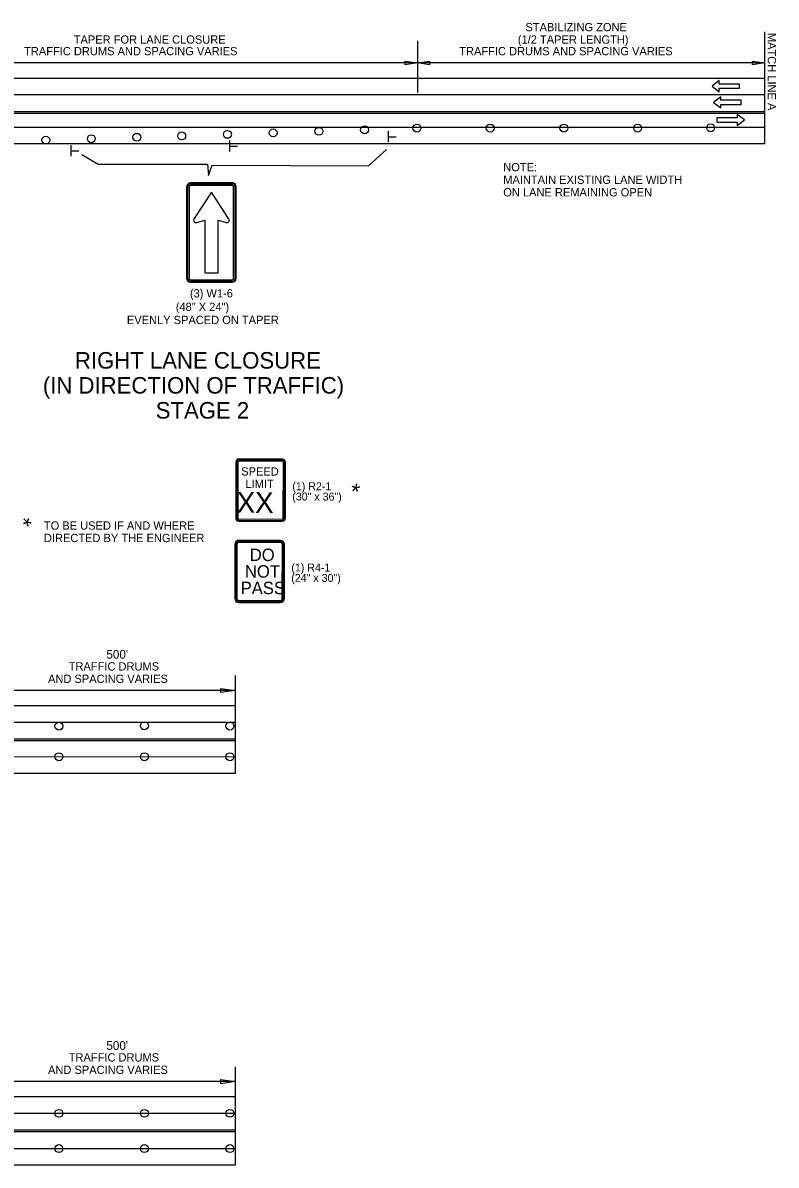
# Model space of a CAD drawing. Extents: x 1930579 to 1938013, y 596452 to 597673.
# Drawn here: x 1934532 to 1935078, y 596702 to 597530 of the extents above; entities that cross this region are included whole.
import ezdxf

# ---------------------------------------------------------------- set-up
doc = ezdxf.new("R2010")
doc.units = 0
for name, color, linetype in [('Default', 7, 'Continuous'), ('P_TC_Signs_Permanent', 7, 'Continuous'), ('R_Border', 7, 'Continuous'), ('R_Striping', 7, 'Continuous')]:
    doc.layers.add(name, color=color, linetype=linetype)

msp = doc.modelspace()

# ---------------------------------------------------------------- linework, layer by layer
at = {"layer": 'Default'}
for p, q in [((1935069.92, 597523.93), (1935069.92, 597466.19)), ((1934818.18, 597517.31), (1934818.18, 597480.01)), ((1934818.18, 597501.43), (1934450.97, 597501.43)), ((1934809.32, 597500.1), (1934809.32, 597502.76)), ((1934809.32, 597502.76), (1934818.18, 597501.43)), ((1934818.18, 597501.43), (1934809.32, 597500.1)), ((1934818.18, 597501.43), (1934827.05, 597502.76)), ((1935069.92, 597501.43), (1934818.18, 597501.43)), ((1934827.05, 597500.1), (1934818.18, 597501.43)), ((1934827.05, 597502.76), (1934827.05, 597500.1)), ((1935061.06, 597500.1), (1935061.06, 597502.76)), ((1935061.06, 597502.76), (1935069.92, 597501.43)), ((1935069.92, 597501.43), (1935061.06, 597500.1)), ((1935069.92, 597490.19), (1933755.41, 597490.19)), ((1935069.92, 597478.19), (1933755.41, 597478.19)), ((1935069.92, 597465.96), (1933755.41, 597465.96)), ((1935069.92, 597464.81), (1933755.41, 597464.81)), ((1935069.92, 597466.19), (1935069.92, 597442.63)), ((1935069.92, 597454.63), (1933755.41, 597454.63)), ((1934797.19, 597443.96), (1934797.19, 597451.94)), ((1934797.31, 597447.93), (1934802.76, 597447.93)), ((1935069.92, 597442.63), (1933755.41, 597442.63)), ((1934567.27, 597433.69), (1934567.27, 597441.67)), ((1934682.23, 597437.18), (1934682.23, 597445.16)), ((1934682.35, 597441.15), (1934687.8, 597441.15)), ((1934567.39, 597437.66), (1934572.84, 597437.66)), ((1934686.11, 597057.24), (1934686.11, 597010.74)), ((1934686.11, 597046.45), (1934521.71, 597046.45)), ((1934675.8, 597044.9), (1934675.8, 597047.99)), ((1934675.8, 597047.99), (1934686.11, 597046.45)), ((1934686.11, 597046.45), (1934675.8, 597044.9)), ((1934686.11, 597035.46), (1933682.42, 597035.46)), ((1933682.42, 597023.46), (1934686.11, 597023.46)), ((1934686.11, 597011.23), (1933682.42, 597011.23)), ((1934686.11, 597010.08), (1933682.42, 597010.08)), ((1934686.11, 597010.74), (1934686.11, 596986.31)), ((1933682.42, 596998.31), (1934686.11, 596998.53)), ((1934686.11, 596986.31), (1933682.42, 596986.31)), ((1934686.11, 596773.75), (1934686.11, 596727.25)), ((1934686.11, 596762.96), (1934521.71, 596762.96)), ((1934675.8, 596761.41), (1934675.8, 596764.5)), ((1934675.8, 596764.5), (1934686.11, 596762.96)), ((1934686.11, 596762.96), (1934675.8, 596761.41)), ((1934686.11, 596751.97), (1933682.42, 596751.97)), ((1933682.42, 596739.97), (1934686.11, 596739.97)), ((1934686.11, 596727.74), (1933682.42, 596727.74)), ((1934686.11, 596726.59), (1933682.42, 596726.59)), ((1934686.11, 596727.25), (1934686.11, 596702.39)), ((1933682.42, 596714.39), (1934686.11, 596714.39)), ((1934686.11, 596702.39), (1933682.42, 596702.39))]:
    msp.add_line(p, q, dxfattribs=at)
for centre in [(1934746.8, 597451.82), (1934779.95, 597452.92), (1934817.9, 597454.14), (1934870.98, 597454.14), (1934924.45, 597454.14), (1934977.92, 597454.15), (1935030.83, 597454.41), (1934548.84, 597445.39), (1934581.82, 597446.43), (1934614.81, 597447.48), (1934647.34, 597448.51), (1934680.49, 597449.61), (1934713.65, 597450.71), (1934558.32, 597020.59), (1934620.32, 597020.91), (1934682.32, 597020.68), (1934558.32, 596998.42), (1934620.32, 596998.42), (1934682.32, 596998.42), (1934558.32, 596739.96), (1934620.32, 596739.96), (1934682.32, 596739.96), (1934558.32, 596714.39), (1934620.32, 596714.39), (1934682.32, 596714.39)]:
    msp.add_circle(centre, 2.87, dxfattribs=at)
at = {"layer": 'P_TC_Signs_Permanent'}
for p, q in [((1934684.07, 597414.37), (1934653.69, 597414.37)), ((1934684.07, 597413.62), (1934653.69, 597413.62)), ((1934650.88, 597411.56), (1934650.88, 597345.18)), ((1934651.63, 597411.56), (1934651.63, 597345.18)), ((1934652.75, 597411.56), (1934652.75, 597345.18)), ((1934684.07, 597412.49), (1934653.69, 597412.49)), ((1934685, 597345.18), (1934685, 597411.56)), ((1934686.13, 597345.18), (1934686.13, 597411.56)), ((1934686.88, 597345.18), (1934686.88, 597411.56)), ((1934653.69, 597344.24), (1934684.07, 597344.24)), ((1934653.69, 597343.12), (1934684.07, 597343.12)), ((1934653.69, 597342.37), (1934684.07, 597342.37)), ((1934686.59, 597212.04), (1934686.49, 597171.54)), ((1934687.15, 597212.04), (1934687.05, 597171.54)), ((1934688.09, 597212.04), (1934687.99, 597171.54)), ((1934720.34, 597214.21), (1934688.84, 597214.29)), ((1934720.34, 597213.65), (1934688.84, 597213.73)), ((1934720.34, 597212.71), (1934688.84, 597212.79)), ((1934720.99, 597171.46), (1934721.09, 597211.96)), ((1934721.92, 597171.46), (1934722.03, 597211.96)), ((1934722.49, 597171.45), (1934722.59, 597211.95)), ((1934688.73, 597169.85), (1934720.23, 597169.77)), ((1934688.73, 597169.29), (1934720.23, 597169.21)), ((1934688.74, 597170.79), (1934720.23, 597170.71)), ((1934685.87, 597152.35), (1934685.78, 597113.35)), ((1934686.47, 597152.35), (1934686.38, 597113.35)), ((1934687.37, 597152.35), (1934687.28, 597113.35)), ((1934718.88, 597155.27), (1934688.88, 597155.35)), ((1934718.88, 597154.67), (1934688.88, 597154.75)), ((1934718.88, 597153.77), (1934688.88, 597153.85)), ((1934720.28, 597113.27), (1934720.37, 597152.27)), ((1934721.18, 597113.27), (1934721.27, 597152.27)), ((1934721.78, 597113.26), (1934721.87, 597152.26)), ((1934688.77, 597111.85), (1934718.77, 597111.77)), ((1934688.77, 597110.95), (1934718.77, 597110.87)), ((1934688.77, 597110.35), (1934718.77, 597110.27))]:
    msp.add_line(p, q, dxfattribs=at)
for points in [[(1934681.32, 597388.63), (1934668.88, 597407.62), (1934656.47, 597388.62)], [(1934658.25, 597385.67), (1934664, 597387.39), (1934664, 597349.12), (1934673.75, 597349.12), (1934673.75, 597387.39), (1934679.5, 597385.63)]]:
    msp.add_lwpolyline(points, dxfattribs=at)
for centre, radius, start, end in [((1934653.69, 597411.56), 2.81, 90, 180), ((1934653.69, 597411.56), 2.06, 90, 180), ((1934684.07, 597411.56), 2.81, 360, 90), ((1934684.07, 597411.56), 2.06, 360, 90), ((1934653.69, 597411.56), 0.938, 90, 180), ((1934684.07, 597411.56), 0.938, 360, 90), ((1934657.76, 597387.36), 1.76, 146.59943, 285.96908), ((1934593.67, 597429.62), 75, 326.59943, 326.85697), ((1934680, 597387.36), 1.8, 254.03093, 33.47548), ((1934744.06, 597429.72), 75, 213.2286, 213.47548), ((1934653.69, 597345.18), 2.81, 180, 270), ((1934653.69, 597345.18), 2.06, 180, 270), ((1934653.69, 597345.18), 0.937, 180, 270), ((1934684.07, 597345.18), 2.81, 270, 360), ((1934684.07, 597345.18), 2.06, 270, 360), ((1934684.07, 597345.18), 0.938, 270, 360), ((1934688.84, 597212.04), 2.25, 89.85705, 179.85705), ((1934688.84, 597212.04), 1.69, 89.85705, 179.85705), ((1934688.84, 597212.04), 0.75, 89.85705, 179.85705), ((1934720.34, 597211.96), 2.25, 359.85705, 89.85705), ((1934720.34, 597211.96), 1.69, 359.85705, 89.85705), ((1934720.34, 597211.96), 0.75, 359.85705, 89.85705), ((1934688.74, 597171.54), 2.25, 179.85705, 269.85705), ((1934688.74, 597171.54), 1.69, 179.85705, 269.85705), ((1934688.74, 597171.54), 0.75, 179.85705, 269.85705), ((1934720.24, 597171.46), 1.69, 269.85705, 359.85705), ((1934720.24, 597171.46), 0.75, 269.85705, 359.85705), ((1934720.24, 597171.46), 2.25, 269.85705, 359.85705), ((1934688.87, 597152.35), 3, 89.85705, 179.85705), ((1934688.87, 597152.35), 2.4, 89.85705, 179.85705), ((1934688.87, 597152.35), 1.5, 89.85705, 179.85705), ((1934718.87, 597152.27), 3, 359.85705, 89.85705), ((1934718.87, 597152.27), 2.4, 359.85705, 89.85705), ((1934718.87, 597152.27), 1.5, 359.85705, 89.85705), ((1934688.78, 597113.35), 3, 179.85705, 269.85705), ((1934688.78, 597113.35), 2.4, 179.85705, 269.85705), ((1934688.78, 597113.35), 1.5, 179.85705, 269.85705), ((1934718.78, 597113.27), 2.4, 269.85705, 359.85705), ((1934718.78, 597113.27), 1.5, 269.85705, 359.85705), ((1934718.78, 597113.27), 3, 269.85705, 359.85705)]:
    msp.add_arc(centre, radius, start, end, dxfattribs=at)
at = {"layer": 'R_Border'}
msp.add_lwpolyline([(1934574.95, 597435.05), (1934586.76, 597428.1), (1934665.96, 597428.1), (1934666.66, 597419.75), (1934669.44, 597427.4), (1934782.69, 597426.71), (1934795.89, 597438.53)], dxfattribs=at)
at = {"layer": 'R_Striping'}
for points in [[(1935037.08, 597488.56), (1935031.88, 597484.56), (1935037.08, 597480.56), (1935037.08, 597483.06), (1935051.79, 597483.06), (1935051.79, 597486.06), (1935037.08, 597486.06)], [(1935038.13, 597476.78), (1935032.94, 597472.78), (1935038.13, 597468.78), (1935038.13, 597471.28), (1935052.84, 597471.28), (1935052.84, 597474.28), (1935038.13, 597474.28)], [(1935050.05, 597456.05), (1935055.25, 597460.05), (1935050.05, 597464.05), (1935050.05, 597461.55), (1935035.34, 597461.55), (1935035.34, 597458.55), (1935050.05, 597458.55)]]:
    msp.add_lwpolyline(points, close=True, dxfattribs=at)

# ---------------------------------------------------------------- texts
at = {"layer": 'Default'}
for s, height, rotation, p in [('STABILIZING ZONE', 6, 360, (1934896.55, 597524.36)), ('TAPER FOR LANE CLOSURE', 6, 360, (1934569.07, 597515.36)), ('(1/2 TAPER LENGTH)', 6, 360, (1934891.03, 597515.36)), ('MATCH LINE A', 5.9996, 270, (1935072.23, 597523.18)), ('TRAFFIC DRUMS AND SPACING VARIES', 6, 360, (1934533.1, 597506.93)), ('TRAFFIC DRUMS AND SPACING VARIES', 6, 360, (1934848.58, 597506.93)), ('RIGHT LANE CLOSURE', 12, 360, (1934569.93, 597279.8)), ('(IN DIRECTION OF TRAFFIC)', 12, 360, (1934546.68, 597261.68)), ('STAGE 2', 12, 360, (1934628.51, 597243.56)), ("500'", 6.336, 360, (1934592.72, 597069.54)), ('TRAFFIC DRUMS ', 6, 360, (1934565.43, 597060.96)), ('AND SPACING VARIES', 6, 360, (1934550.43, 597051.96)), ("500'", 6.336, 360, (1934592.72, 596785.97)), ('TRAFFIC DRUMS ', 6, 360, (1934565.43, 596777.51)), ('AND SPACING VARIES', 6, 360, (1934550.43, 596768.51))]:
    msp.add_text(s, height=height, rotation=rotation, dxfattribs=at).set_placement(p)
at = {"layer": 'P_TC_Signs_Permanent'}
for s, height, rotation, p in [('SPEED', 6, 359.85705, (1934690.49, 597202.28)), ('LIMIT', 6, 359.85705, (1934693.56, 597193.28)), ('XX', 15, 359.85705, (1934687.2, 597175.29)), ('DO', 9, 359.85705, (1934696.67, 597140.33)), ('NOT', 9, 359.81669, (1934693.16, 597128.34)), ('PASS', 9, 359.85705, (1934690.08, 597116.34))]:
    msp.add_text(s, height=height, rotation=rotation, dxfattribs=at).set_placement(p)
at = {"layer": 'R_Border'}
for s, height, rotation, p in [('NOTE:', 6, 360, (1934880.47, 597422.84)), ('MAINTAIN EXISTING LANE WIDTH', 6, 360, (1934880.47, 597413.73)), ('ON LANE REMAINING OPEN', 6, 360, (1934880.47, 597404.62)), ('(3) W1-6', 6, 0.00754, (1934653.27, 597331.37)), ('(48" X 24")', 6, 0.00754, (1934643.04, 597321.57)), ('EVENLY SPACED ON TAPER', 6, 0.00754, (1934607.63, 597312.07)), ('(30" x 36")', 5.76, 359.85705, (1934727.52, 597184.2)), ('(1) R2-1', 5.76, 359.85705, (1934727.54, 597191.69)), ('*', 12, 134.85705, (1934782.01, 597197.41)), ('*', 12, 45, (1934539.25, 597160.1)), ('TO BE USED IF AND WHERE', 6, 360, (1934547.43, 597163.04)), ('DIRECTED BY THE ENGINEER', 6, 360, (1934547.43, 597154.04)), ('(1) R4-1', 5.76, 359.85705, (1934726.83, 597132.75)), ('(24" x 30")', 5.76, 359.85705, (1934726.81, 597125.26))]:
    msp.add_text(s, height=height, rotation=rotation, dxfattribs=at).set_placement(p)

doc.saveas('drawing.dxf')
